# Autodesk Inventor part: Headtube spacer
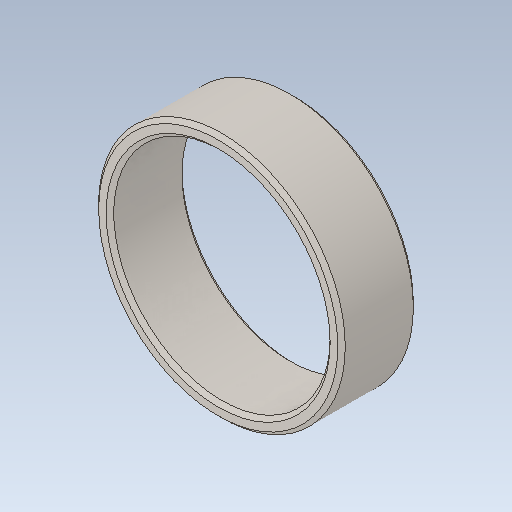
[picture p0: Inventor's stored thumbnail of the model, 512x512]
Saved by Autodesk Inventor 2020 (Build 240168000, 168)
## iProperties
Created: 2017-09
Part Number: Headtube spacer
Material: SolidWorks DIN Materials|1.4541 (X6CrNiTi18-10)|143
Document SubType Name: Modeling
Designer: Tomasz
Density: 7.9 g/cm^3
Appearance: 198,193,188
Sending System: SolidWorks 2017
Last Author: Tomasz
Last Saved: 2017-09-27
Author: Tomasz
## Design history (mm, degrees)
chamfer "Chamfer1"
node "Bryła1"
